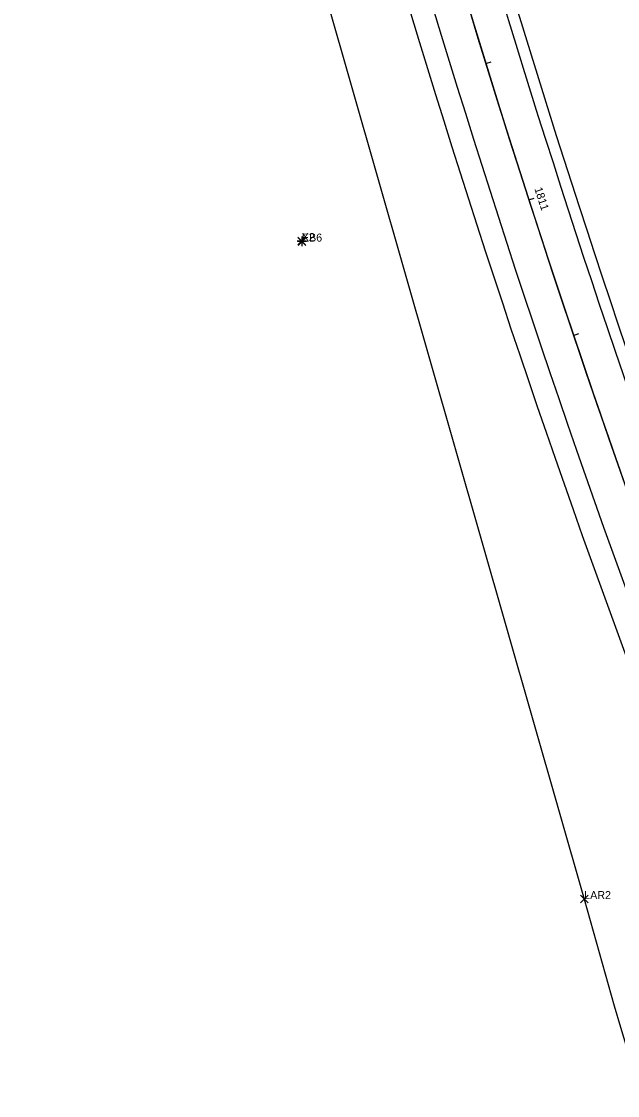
# Model space of a CAD drawing. Extents: x 6334 to 41599, y 9030 to 59113.
# Drawn here: x 20634.4 to 20842.8, y 34759.9 to 35135.8 of the extents above; entities that cross this region are included whole.
import ezdxf

# ---------------------------------------------------------------- set-up
doc = ezdxf.new("R2010")
doc.units = 0
for name, color, linetype in [('GE_X_CL_20', 7, 'Continuous'), ('GE_X_CL_50', 7, 'Continuous'), ('GK_Visualization', 7, 'Continuous'), ('PM_X_Lane_Line', 7, 'Continuous'), ('PV_X_EOP', 7, 'Continuous'), ('PV_X_Shoulder', 7, 'Continuous'), ('RW_X_Esmt_LA', 7, 'Continuous')]:
    doc.layers.add(name, color=color, linetype=linetype)

msp = doc.modelspace()

# ---------------------------------------------------------------- linework, layer by layer
at = {"layer": 'GE_X_CL_20'}
for p, q in [((20796.76, 35121.08), (20798.68, 35121.67)), ((20811.8, 35073.39), (20813.7, 35074)), ((20827.44, 35025.9), (20829.34, 35026.54))]:
    msp.add_line(p, q, dxfattribs=at)
msp.add_arc((24529.94, 36271.9), 3906.53, 186.21667, 209.21667, dxfattribs=at)
at = {"layer": 'GE_X_CL_50'}
msp.add_arc((32581.78, 39251.96), 12277.67, 194.525, 202.716667, dxfattribs=at)
at = {"layer": 'GK_Visualization'}
for p, q in [((20733.94, 35058.94), (20730.82, 35058.94)), ((20734.01, 35058.75), (20730.89, 35058.75)), ((20731.05, 35057.61), (20733.72, 35060.28)), ((20731.05, 35060.28), (20733.72, 35057.61)), ((20731.11, 35057.41), (20733.78, 35060.08)), ((20731.11, 35060.08), (20733.78, 35057.41)), ((20732.38, 35060.5), (20732.38, 35057.38)), ((20732.45, 35060.31), (20732.45, 35057.19)), ((20829.83, 34827.33), (20832.5, 34830)), ((20829.83, 34830), (20832.5, 34827.33))]:
    msp.add_line(p, q, dxfattribs=at)
for centre, radius, start, end in [((28229.01, 37734.18), 7639.44, 189.175, 202.716667), ((28229.01, 37734.18), 7639.44, 189.175, 202.716667), ((32581.78, 39251.96), 12277.67, 194.525, 202.716667), ((32581.78, 39251.96), 12277.67, 194.525, 202.716667), ((24529.91, 36271.94), 3906.53, 186.21497, 209.2138), ((24529.91, 36271.94), 3906.53, 186.21497, 209.2138), ((24529.94, 36271.9), 3906.53, 186.21667, 209.21667), ((24529.94, 36271.9), 3906.53, 186.21667, 209.21667)]:
    msp.add_arc(centre, radius, start, end, dxfattribs=at)
at = {"layer": 'PM_X_Lane_Line'}
for centre, radius, start, end in [((28229.01, 37734.18), 7639.44, 189.175, 202.716667), ((24529.94, 36271.9), 3906.53, 186.21667, 209.21667), ((24529.94, 36271.9), 3906.53, 191.33607, 209.21667)]:
    msp.add_arc(centre, radius, start, end, dxfattribs=at)
at = {"layer": 'PV_X_EOP'}
for centre, radius, start, end in [((28229.01, 37734.18), 7627.44, 191.807877, 202.716667), ((24529.94, 36271.9), 3918.53, 191.33607, 209.21667), ((24531.79, 36272.61), 3896.49, 192.87045, 209.21252)]:
    msp.add_arc(centre, radius, start, end, dxfattribs=at)
at = {"layer": 'PV_X_Shoulder'}
for centre, radius, start, end in [((28229.01, 37734.18), 7619.44, 191.815419, 202.716667), ((24529.94, 36271.9), 3926.53, 191.34141, 209.21667), ((24529.94, 36271.9), 3890.53, 192.86631, 209.21667)]:
    msp.add_arc(centre, radius, start, end, dxfattribs=at)
at = {"layer": 'RW_X_Esmt_LA'}
msp.add_line((20634.38, 35516.75), (20831.17, 34828.67), dxfattribs=at)
msp.add_arc((23569.82, 35580.33), 2839.93, 195.3477, 205.35619, dxfattribs=at)

# ---------------------------------------------------------------- texts
at = {"layer": 'GE_X_CL_20'}
msp.add_text('1811', height=2.8, rotation=287.8662, dxfattribs=at).set_placement((20813.7, 35077.28))
at = {"layer": 'GK_Visualization'}
for s, p in [('X2', (20732.38, 35058.94)), ('EB6', (20732.45, 35058.75)), ('LAR2', (20831.17, 34828.67))]:
    msp.add_text(s, height=2.8, dxfattribs=at).set_placement(p)

doc.saveas('drawing.dxf')
